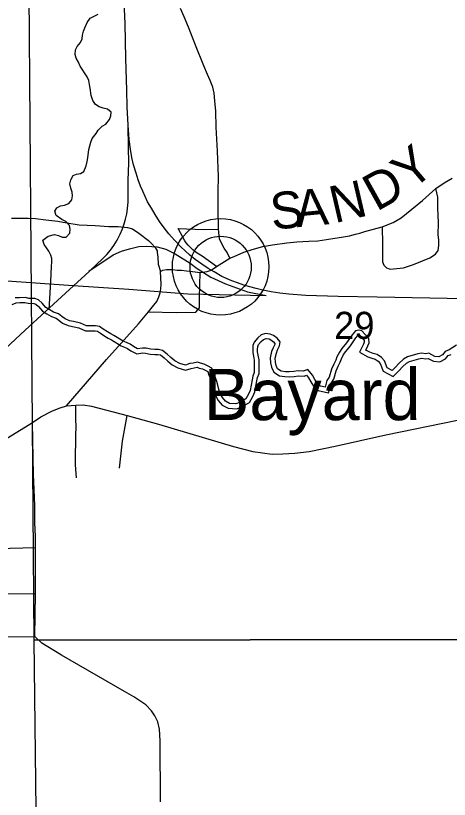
# Model space of a CAD drawing. Extents: x 0 to 34, y 0 to 22.
# Drawn here: x 7.12 to 7.789, y 17.784 to 18.992 of the extents above; entities that cross this region are included whole.
import ezdxf

# ---------------------------------------------------------------- set-up
doc = ezdxf.new("R2010")
doc.units = 0
doc.layers.add('Default', color=7, linetype='Continuous')

msp = doc.modelspace()

# ---------------------------------------------------------------- linework, layer by layer
at = {"layer": 'Default'}
for p, q in [((7.4361, 18.6047), (7.4361, 18.6047)), ((6.9952, 18.1679), (7.1508, 18.1722))]:
    msp.add_line(p, q, dxfattribs=at)
for points in [[(7.8123, 18.5555), (7.6771, 18.5582), (7.6173, 18.5593), (7.5676, 18.5607), (7.5413, 18.5629), (7.5275, 18.5644), (7.514, 18.5664), (7.5011, 18.5688), (7.4909, 18.5713), (7.4813, 18.5737), (7.4721, 18.5767), (7.4623, 18.5799), (7.4535, 18.5834), (7.4382, 18.5901), (7.4259, 18.597), (7.417, 18.6021), (7.4072, 18.6087), (7.3971, 18.6161), (7.3887, 18.6229), (7.3816, 18.6293), (7.3746, 18.6358), (7.365, 18.6459), (7.3563, 18.6555), (7.349, 18.6649), (7.3418, 18.6749), (7.3351, 18.6852), (7.3294, 18.6952), (7.3236, 18.7051), (7.3196, 18.7134), (7.3161, 18.7214), (7.3126, 18.7293), (7.3092, 18.7389), (7.3057, 18.7492), (7.302, 18.7619), (7.2995, 18.7731), (7.2971, 18.7859), (7.2951, 18.8011), (7.2936, 18.823), (7.2921, 18.8513), (7.2913, 18.8772), (7.29, 18.926), (7.2888, 18.9797), (7.2865, 19.0366)], [(7.1987, 18.3905), (7.26, 18.4618), (7.3096, 18.5171), (7.325, 18.5354), (7.3332, 18.5455), (7.3378, 18.5513), (7.3411, 18.5583), (7.3431, 18.5648), (7.3439, 18.5707), (7.3442, 18.5781), (7.3435, 18.5978), (7.347, 18.5998), (7.3526, 18.6005), (7.3613, 18.6005), (7.3692, 18.5998), (7.3758, 18.5994), (7.3836, 18.5985), (7.393, 18.5975), (7.4044, 18.5961), (7.4151, 18.5974), (7.4215, 18.5998), (7.4298, 18.6051), (7.4381, 18.6105), (7.4503, 18.6181), (7.4462, 18.6267), (7.4414, 18.6338), (7.4372, 18.6411), (7.4346, 18.6479), (7.4327, 18.6627), (7.4321, 18.6959), (7.4324, 18.7206), (7.4327, 18.744), (7.4312, 18.783), (7.4291, 18.8202), (7.4287, 18.8448), (7.4274, 18.8608), (7.4261, 18.8724), (7.4239, 18.8819), (7.42, 18.8921), (7.4159, 18.9014), (7.4103, 18.9144), (7.3972, 18.9465), (7.3864, 18.9741), (7.38, 18.9903), (7.3743, 19.0031)], [(7.172, 18.5392), (7.1743, 18.5815), (7.1749, 18.5944), (7.1755, 18.6055), (7.1762, 18.6124), (7.1758, 18.6177), (7.1742, 18.623), (7.1715, 18.6287), (7.1676, 18.6339), (7.1641, 18.6392), (7.1622, 18.6457), (7.1701, 18.6522), (7.1799, 18.6547), (7.186, 18.6532), (7.1918, 18.6506), (7.1978, 18.6507), (7.2035, 18.6565), (7.2042, 18.6626), (7.203, 18.6687), (7.1976, 18.6747), (7.1914, 18.6777), (7.1826, 18.684), (7.1807, 18.6905), (7.1836, 18.6958), (7.1893, 18.6986), (7.1954, 18.6998), (7.2022, 18.7022), (7.2067, 18.7083), (7.2078, 18.7144), (7.2073, 18.7201), (7.2054, 18.7258), (7.2038, 18.7326), (7.2052, 18.7391), (7.2089, 18.7453), (7.2142, 18.7476), (7.2199, 18.7488), (7.2252, 18.7516), (7.2289, 18.7604), (7.2304, 18.7669), (7.2314, 18.7726), (7.2332, 18.7856), (7.2347, 18.7913), (7.2361, 18.797), (7.2383, 18.8028), (7.2443, 18.8101), (7.2473, 18.8155), (7.2533, 18.8216), (7.259, 18.8247), (7.265, 18.8321), (7.2668, 18.8374), (7.2675, 18.8431), (7.2618, 18.8476), (7.2549, 18.8491), (7.2488, 18.8513), (7.2434, 18.855), (7.2392, 18.861), (7.2368, 18.869), (7.2348, 18.8804), (7.234, 18.8857), (7.2328, 18.8922), (7.2304, 18.8974), (7.2196, 18.9141), (7.2172, 18.9201), (7.2134, 18.9265), (7.2121, 18.9322), (7.2124, 18.9391), (7.215, 18.9444), (7.2199, 18.9506), (7.2225, 18.9563), (7.2232, 18.9621), (7.2247, 18.9678), (7.2269, 18.9732), (7.2306, 18.9812), (7.2351, 18.9881), (7.2411, 18.9912), (7.2472, 18.994)], [(7.0659, 18.4436), (7.1351, 18.5072), (7.2091, 18.5755), (7.2334, 18.5976), (7.246, 18.6094), (7.2531, 18.6161), (7.2607, 18.6238), (7.2664, 18.6306), (7.2717, 18.6379), (7.2769, 18.6459), (7.2815, 18.6552), (7.285, 18.6636), (7.2876, 18.6709), (7.2896, 18.6782), (7.2917, 18.6865), (7.2928, 18.6944), (7.2936, 18.7049), (7.2936, 18.7165), (7.2936, 18.7379), (7.2944, 18.7652), (7.2942, 18.7888), (7.2936, 18.823)], [(7.4503, 18.6181), (7.4571, 18.6207), (7.472, 18.6276), (7.4848, 18.6317), (7.5013, 18.6359), (7.5161, 18.6386), (7.538, 18.6416), (7.5536, 18.6431), (7.5721, 18.6442), (7.5857, 18.6449), (7.5995, 18.6468), (7.6123, 18.6489), (7.6226, 18.6504), (7.6349, 18.6528), (7.6437, 18.6551), (7.6504, 18.6569), (7.6582, 18.6594), (7.6852, 18.6665), (7.702, 18.6731), (7.7143, 18.6804), (7.731, 18.6936), (7.7472, 18.7071), (7.7678, 18.7253), (7.7807, 18.734), (7.7927, 18.7415)], [(7.6852, 18.6665), (7.6855, 18.6395), (7.6856, 18.6295), (7.6856, 18.6193), (7.6857, 18.6124), (7.6874, 18.6071), (7.6915, 18.6032), (7.6975, 18.6013), (7.7181, 18.603), (7.7333, 18.6082), (7.7472, 18.6141), (7.7583, 18.6188), (7.7672, 18.6244), (7.7713, 18.6302), (7.7725, 18.6379), (7.7722, 18.6465), (7.7715, 18.6541), (7.7717, 18.6728), (7.7711, 18.6959), (7.771, 18.7119), (7.7678, 18.7253)], [(7.1139, 18.68), (7.1278, 18.6798), (7.1395, 18.6798), (7.1506, 18.6793), (7.1665, 18.6774), (7.1851, 18.6752), (7.1993, 18.6728), (7.2183, 18.6697), (7.2429, 18.6687), (7.264, 18.6668), (7.2783, 18.6668), (7.2927, 18.6653), (7.3003, 18.6631), (7.3101, 18.6566), (7.3248, 18.6452), (7.3297, 18.6407), (7.3353, 18.6347), (7.3383, 18.6292), (7.3385, 18.6271)], [(7.3708, 18.6638), (7.4097, 18.6622), (7.4327, 18.6627)], [(7.4298, 18.6051), (7.4077, 18.6211), (7.4, 18.626), (7.3932, 18.6312), (7.3859, 18.6382), (7.383, 18.6416), (7.3809, 18.6447), (7.3708, 18.6638)], [(6.2768, 18.6314), (6.5613, 18.6169), (6.8158, 18.6017), (7.0484, 18.5875), (7.2089, 18.5761)], [(7.2332, 18.5982), (7.2706, 18.6234), (7.2833, 18.629), (7.2955, 18.6327), (7.3101, 18.6363), (7.3221, 18.6366), (7.3384, 18.6355), (7.3515, 18.6321), (7.3662, 18.6249), (7.3891, 18.6103), (7.4001, 18.602), (7.4209, 18.5888), (7.4436, 18.5788), (7.4777, 18.5661), (7.5062, 18.5608)], [(7.3385, 18.6271), (7.3392, 18.6198), (7.3398, 18.6089), (7.3435, 18.5978)], [(7.325, 18.5354), (7.3675, 18.5345), (7.3979, 18.5351), (7.4033, 18.5418), (7.4033, 18.557), (7.4044, 18.5961)], [(7.2089, 18.5761), (7.2946, 18.5706), (7.3856, 18.5631), (7.5062, 18.5608)], [(7.1263, 18.5572), (7.1195, 18.5568)], [(7.6154, 18.4663), (7.6135, 18.4609), (7.6105, 18.4549), (7.6071, 18.4469), (7.6034, 18.4347), (7.6, 18.4294), (7.597, 18.4195), (7.5902, 18.421), (7.5849, 18.4259), (7.5814, 18.4312), (7.5776, 18.438), (7.5707, 18.4467), (7.5635, 18.444), (7.5555, 18.4443), (7.5487, 18.4432), (7.5419, 18.4428), (7.5362, 18.4431), (7.5293, 18.4442), (7.524, 18.4476), (7.5217, 18.4525), (7.5205, 18.4578), (7.5201, 18.4639), (7.522, 18.4719), (7.5238, 18.4768), (7.5269, 18.4829), (7.5276, 18.489), (7.523, 18.4946), (7.5177, 18.4988), (7.5127, 18.501), (7.5055, 18.5018), (7.4987, 18.4998), (7.4934, 18.4953), (7.4877, 18.4888), (7.4858, 18.4835), (7.4855, 18.4778), (7.4855, 18.4728), (7.4867, 18.4671), (7.4879, 18.4607), (7.4879, 18.4554), (7.4879, 18.4489), (7.488, 18.4417), (7.4857, 18.4364), (7.4846, 18.4307), (7.4816, 18.4144), (7.479, 18.4083), (7.4749, 18.4014), (7.465, 18.3957), (7.4597, 18.3934), (7.4499, 18.3941), (7.4434, 18.3975), (7.4388, 18.4032), (7.4357, 18.4085), (7.4338, 18.4141), (7.4303, 18.4278), (7.4284, 18.4335), (7.4249, 18.4407), (7.4226, 18.4486), (7.4158, 18.452), (7.4108, 18.455), (7.4051, 18.4561), (7.4002, 18.458), (7.3937, 18.4564), (7.3888, 18.4557), (7.382, 18.4534), (7.3732, 18.456), (7.3656, 18.4601), (7.3595, 18.465), (7.3538, 18.4703), (7.3465, 18.4759), (7.3401, 18.4774), (7.3348, 18.4774), (7.3287, 18.4778), (7.3215, 18.4792), (7.3158, 18.4796), (7.3082, 18.4784), (7.3017, 18.4818), (7.2968, 18.4856), (7.2911, 18.4882), (7.2861, 18.4901), (7.2716, 18.4987), (7.2667, 18.5014), (7.2617, 18.5044), (7.2553, 18.5085), (7.2495, 18.5127), (7.2435, 18.5138), (7.2294, 18.5137), (7.2199, 18.5182), (7.2093, 18.5204), (7.2032, 18.5215), (7.1963, 18.5245), (7.1914, 18.5283), (7.1864, 18.5325), (7.1784, 18.5351), (7.172, 18.5388), (7.1666, 18.5422), (7.1609, 18.549), (7.1552, 18.5539), (7.1495, 18.5558), (7.1407, 18.5561), (7.1354, 18.5576), (7.1263, 18.5572)], [(7.1147, 18.5468), (7.1211, 18.5493), (7.1267, 18.5496)], [(7.1267, 18.5496), (7.1346, 18.55), (7.1396, 18.5486), (7.1481, 18.5483), (7.1514, 18.5472), (7.1555, 18.5437), (7.1616, 18.5365), (7.168, 18.5324), (7.1753, 18.5281), (7.1827, 18.5257), (7.1866, 18.5224), (7.1925, 18.518), (7.201, 18.5142), (7.2078, 18.513), (7.2175, 18.511), (7.2277, 18.5061), (7.2428, 18.5062), (7.2465, 18.5055), (7.251, 18.5023), (7.2577, 18.4979), (7.2629, 18.4948), (7.2679, 18.4921), (7.2828, 18.4832), (7.2881, 18.4812), (7.2928, 18.479), (7.2976, 18.4754), (7.3069, 18.4705), (7.3161, 18.472), (7.3205, 18.4717), (7.3277, 18.4702), (7.3346, 18.4698), (7.3392, 18.4699), (7.3432, 18.4689), (7.3489, 18.4645), (7.3546, 18.4593), (7.3614, 18.4538), (7.3703, 18.4489), (7.3821, 18.4454), (7.3906, 18.4483), (7.3952, 18.449), (7.3997, 18.4501), (7.403, 18.4488), (7.408, 18.4478), (7.4121, 18.4454), (7.4163, 18.4433), (7.4178, 18.4379), (7.4214, 18.4306), (7.4231, 18.4256), (7.4265, 18.412), (7.4288, 18.4053), (7.4325, 18.3989), (7.4385, 18.3915), (7.4477, 18.3867), (7.461, 18.3857), (7.4685, 18.3889), (7.4804, 18.3959), (7.4858, 18.4048), (7.4889, 18.4122), (7.492, 18.4293), (7.493, 18.4342), (7.4955, 18.4402), (7.4955, 18.449), (7.4955, 18.4554), (7.4954, 18.4614), (7.4941, 18.4686), (7.4931, 18.4736), (7.4931, 18.4776), (7.4933, 18.4819), (7.4944, 18.4849), (7.4987, 18.4899), (7.5024, 18.493), (7.5062, 18.4941), (7.5107, 18.4936), (7.5137, 18.4923), (7.5177, 18.4892), (7.5197, 18.4867), (7.5195, 18.4851), (7.5169, 18.4798), (7.5147, 18.4741), (7.5125, 18.4645), (7.513, 18.4567), (7.5145, 18.4501), (7.5181, 18.4424), (7.5266, 18.437), (7.5353, 18.4356), (7.5419, 18.4352), (7.5496, 18.4356), (7.556, 18.4367), (7.5647, 18.4364), (7.5682, 18.4377), (7.5713, 18.4338), (7.5749, 18.4273), (7.579, 18.421), (7.5866, 18.414), (7.6023, 18.4106), (7.607, 18.4262), (7.6104, 18.4315), (7.6143, 18.4443), (7.6174, 18.4517), (7.6205, 18.458), (7.6224, 18.4632)], [(7.7994, 18.4839), (7.7881, 18.4766), (7.7824, 18.4743), (7.7779, 18.469), (7.7722, 18.4663), (7.7661, 18.4666), (7.757, 18.4715), (7.7521, 18.4707), (7.7456, 18.4715), (7.7399, 18.4707), (7.724, 18.466), (7.7179, 18.4622), (7.7107, 18.4557), (7.7058, 18.45), (7.7006, 18.445), (7.6926, 18.4492), (7.6887, 18.4598), (7.6841, 18.4651), (7.6776, 18.4696), (7.6712, 18.4711), (7.6662, 18.473), (7.6601, 18.4763), (7.6631, 18.4828), (7.665, 18.4878), (7.6646, 18.4942), (7.6596, 18.5002), (7.6539, 18.5063), (7.649, 18.5074), (7.644, 18.5059), (7.6388, 18.5001), (7.6301, 18.4876), (7.6229, 18.4788), (7.6192, 18.4735), (7.6154, 18.4663)], [(7.6224, 18.4632), (7.6256, 18.4695), (7.629, 18.4742), (7.6362, 18.483), (7.6447, 18.4954), (7.6482, 18.4992), (7.6493, 18.4996), (7.65, 18.4994), (7.654, 18.4952), (7.6572, 18.4913), (7.6574, 18.4889), (7.6562, 18.4858), (7.6503, 18.4731), (7.663, 18.4661), (7.669, 18.4638), (7.6745, 18.4625), (7.679, 18.4594), (7.6821, 18.4559), (7.6864, 18.4438), (7.7018, 18.4359), (7.7113, 18.4448), (7.7162, 18.4504), (7.7225, 18.4562), (7.7271, 18.4591), (7.7415, 18.4632), (7.7457, 18.4638), (7.7522, 18.4631), (7.7557, 18.4636), (7.764, 18.4592), (7.7737, 18.4586), (7.7826, 18.4628), (7.787, 18.468), (7.7916, 18.4698)], [(7.5949, 18.3248), (7.6124, 18.3285), (7.6907, 18.3457), (7.801, 18.3684), (7.8747, 18.3839), (7.9278, 18.3955), (7.9869, 18.4058), (8.0938, 18.4215), (8.1482, 18.4299), (8.2048, 18.4387), (8.4198, 18.4707)], [(7.102, 18.3377), (7.1461, 18.3649), (7.1591, 18.3736), (7.1759, 18.3824), (7.1871, 18.3867), (7.1987, 18.3905), (7.2132, 18.3916), (7.2242, 18.3919), (7.237, 18.3902), (7.2919, 18.3756), (7.3401, 18.3624), (7.4561, 18.3281), (7.4855, 18.3203), (7.5005, 18.3182), (7.5153, 18.3162), (7.5321, 18.3164), (7.5507, 18.3174), (7.5726, 18.3201), (7.5949, 18.3248)], [(7.2139, 18.2795), (7.2125, 18.2998), (7.2124, 18.3077), (7.2125, 18.3152), (7.2125, 18.3216), (7.2128, 18.3285), (7.2128, 18.3361), (7.2129, 18.3438), (7.2137, 18.3597), (7.2132, 18.3685), (7.2132, 18.3769), (7.2132, 18.3916)], [(7.28, 18.2947), (7.2847, 18.3363), (7.2919, 18.3756)], [(7.1481, 18.2738), (7.1477, 18.2839), (7.1461, 18.3649)], [(7.1508, 18.1722), (7.1508, 18.1892), (7.15, 18.2109), (7.1498, 18.2364), (7.1481, 18.2738)], [(7.1499, 18.035), (7.1509, 18.1013), (7.1508, 18.1722)], [(7.0016, 18.1001), (7.0276, 18.1003), (7.0631, 18.1008), (7.1509, 18.1013)], [(6.8262, 18.0322), (7.0019, 18.0341), (7.1499, 18.035)], [(7.3436, 17.78), (7.343, 17.8741), (7.3417, 17.8923), (7.3392, 17.9034), (7.3348, 17.9128), (7.3296, 17.9205), (7.3207, 17.9297), (7.3023, 17.9419), (7.2881, 17.9501), (7.191, 18.0063), (7.1608, 18.0249), (7.1499, 18.035)]]:
    msp.add_lwpolyline(points, dxfattribs=at)
for points in [[(7.1411, 19.0266), (8.1392, 19.0236), (8.1478, 18.0308), (7.1486, 18.0293)], [(7.1486, 18.0293), (8.1478, 18.0308), (8.1673, 17.0247), (7.2555, 17.0252), (7.1604, 17.0251)]]:
    msp.add_lwpolyline(points, close=True, dxfattribs=at)
for radius in [0.0744, 0.0472]:
    msp.add_circle((7.4361, 18.6047), radius, dxfattribs=at)

# ---------------------------------------------------------------- texts
for s, height, rotation, p in [('Y', 0.0568, 40.2741, (7.73, 18.7206)), ('D', 0.0568, 29.1241, (7.6764, 18.6894)), ('N', 0.0568, 13.1176, (7.6116, 18.6718)), ('S', 0.0568, 6.3512, (7.5158, 18.6615)), ('A', 0.0568, 5.4652, (7.5536, 18.6657)), ('29', 0.04186, 0, (7.611, 18.4936)), ('Bayard', 0.07898, 0, (7.4098, 18.3685))]:
    msp.add_text(s, height=height, rotation=rotation, dxfattribs=at).set_placement(p)

doc.saveas('drawing.dxf')
